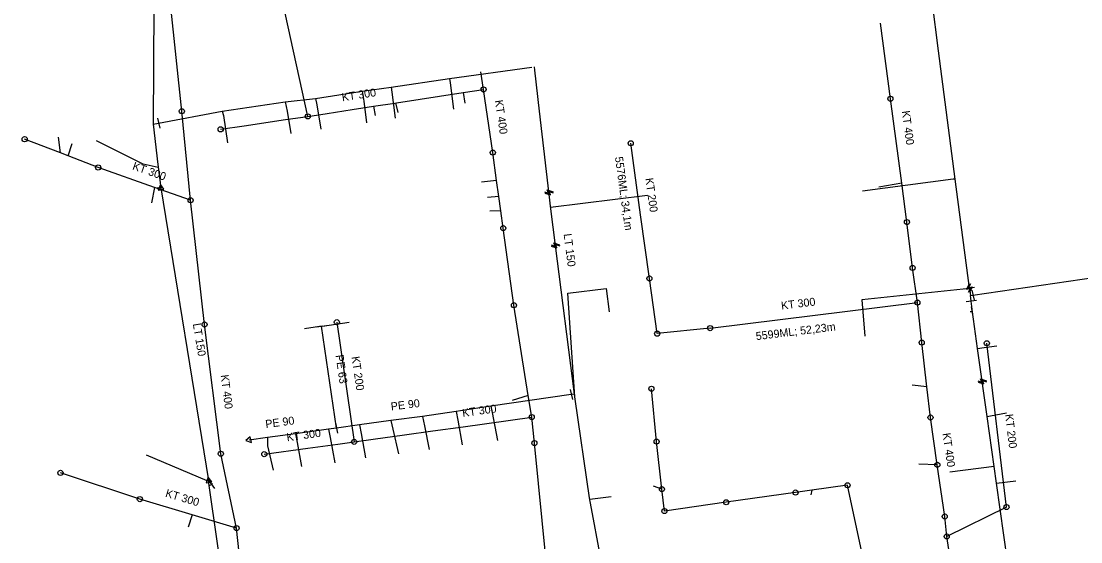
# Model space of a CAD drawing. Extents: x -867696 to -865033, y -1042522 to -1039817.
# Drawn here: x -866602 to -866337.2, y -1040090 to -1039959.9 of the extents above; entities that cross this region are included whole.
import ezdxf

# ---------------------------------------------------------------- set-up
doc = ezdxf.new("R2010")
doc.units = 0
for name, color, linetype in [('KN - jednotna', 7, 'Continuous'), ('KN - popis material', 7, 'Continuous'), ('KN - popis usek delka', 7, 'Continuous'), ('KN - pripojka', 7, 'Continuous'), ('KN - sachta komora', 7, 'Continuous'), ('Level 1', 7, 'Continuous'), ('V - armatura', 7, 'Continuous'), ('V - hydrant', 7, 'Continuous'), ('V - ostatni', 7, 'Continuous'), ('V - popis material', 7, 'Continuous'), ('V - pripojka', 7, 'Continuous'), ('V - rozvadeci', 7, 'Continuous')]:
    doc.layers.add(name, color=color, linetype=linetype)

# ---------------------------------------------------------------- blocks, each defined once
blk = doc.blocks.new('100.M')
at = {"layer": 'Level 1'}
blk.add_circle((0, 0), 1.27, dxfattribs=at)
blk = doc.blocks.new('111')
at = {"layer": 'Level 1'}
for p, q in [((0.42, 0.72), (-0.83, 0)), ((-0.83, 0), (0.42, -0.72)), ((0.42, -0.72), (0.42, 0.72))]:
    blk.add_line(p, q, dxfattribs=at)
blk = doc.blocks.new('147')
at = {"layer": 'Level 1'}
blk.add_line((0, 1.27), (0, -1.27), dxfattribs=at)
blk = doc.blocks.new('156')
at = {"layer": 'Level 1'}
for p, q in [((-0.07, 1.04), (-0.68, -0.3)), ((0.28, 1.04), (-0.19, 0.08)), ((-0.19, 0.08), (0.7, 0.29)), ((0.7, 0.29), (0.02, -1.08)), ((-0.68, -0.3), (0.21, -0.09)), ((0.21, -0.09), (-0.28, -1.08))]:
    blk.add_line(p, q, dxfattribs=at)
blk = doc.blocks.new('150')
at = {"layer": 'Level 1'}
blk.add_line((0, 1.27), (0, -1.27), dxfattribs=at)

msp = doc.modelspace()

# ---------------------------------------------------------------- linework, layer by layer
at = {"layer": 'KN - jednotna'}
for points in [[(-866530.42, -1039983.698), (-866536.083, -1039957.905), (-866537.085, -1039953.342)], [(-866561.894, -1039982.409), (-866564.686, -1039955.577)], [(-866384.771, -1039979.298), (-866387.278, -1039960.4)], [(-866486.47, -1039976.957), (-866487.152, -1039972.545)], [(-866530.42, -1039983.698), (-866525.527, -1039982.947), (-866519.293, -1039981.991), (-866513.939, -1039981.17), (-866508.681, -1039980.364), (-866508.223, -1039980.293), (-866491.558, -1039977.737), (-866486.47, -1039976.957)], [(-866484.157, -1039992.76), (-866486.47, -1039976.957)], [(-866380.63, -1040010.12), (-866381.931, -1040000.41), (-866384.771, -1039979.298)], [(-866559.707, -1040004.648), (-866561.894, -1039982.409)], [(-866552.186, -1039986.929), (-866546.344, -1039986.061), (-866535.938, -1039984.517), (-866530.42, -1039983.698)], [(-866582.782, -1039996.47), (-866590.301, -1039993.583), (-866592.245, -1039992.837), (-866601.176, -1039989.408)], [(-866445.015, -1040024.206), (-866447.202, -1040008.333), (-866449.67, -1039990.42)], [(-866481.542, -1040011.623), (-866482.142, -1040007.293), (-866482.633, -1040003.747), (-866483.194, -1039999.701), (-866484.157, -1039992.76)], [(-866559.707, -1040004.648), (-866568.727, -1040001.452), (-866582.782, -1039996.47)], [(-866556.19, -1040035.705), (-866559.707, -1040004.648)], [(-866478.869, -1040030.903), (-866481.542, -1040011.623)], [(-866379.227, -1040021.559), (-866380.63, -1040010.12)], [(-866378.02, -1040030.23), (-866379.227, -1040021.559)], [(-866443.083, -1040037.995), (-866445.015, -1040024.206)], [(-866474.415, -1040058.848), (-866475.283, -1040053.406), (-866478.869, -1040030.903)], [(-866429.855, -1040036.614), (-866378.02, -1040030.23)], [(-866376.958, -1040040.23), (-866378.02, -1040030.23)], [(-866552.13, -1040067.99), (-866556.19, -1040035.705)], [(-866523.135, -1040035.115), (-866518.82, -1040065.024)], [(-866429.855, -1040036.614), (-866443.083, -1040037.995)], [(-866374.748, -1040058.939), (-866375.653, -1040051.274), (-866376.958, -1040040.23)], [(-866355.75, -1040081.321), (-866360.665, -1040040.386)], [(-866443.21, -1040064.976), (-866444.505, -1040051.755)], [(-866518.82, -1040065.024), (-866514.099, -1040064.368), (-866506.221, -1040063.272), (-866499.129, -1040062.286), (-866491.592, -1040061.237), (-866474.415, -1040058.848)], [(-866473.763, -1040065.329), (-866474.415, -1040058.848)], [(-866373.047, -1040070.778), (-866374.748, -1040058.939)], [(-866541.268, -1040068.103), (-866530.362, -1040066.608), (-866522.911, -1040065.586), (-866518.82, -1040065.024)], [(-866470.797, -1040094.799), (-866473.763, -1040065.329)], [(-866441.88, -1040076.855), (-866443.21, -1040064.976)], [(-866548.186, -1040086.588), (-866552.13, -1040067.99)], [(-866572.376, -1040079.342), (-866592.223, -1040072.779)], [(-866371.193, -1040083.679), (-866373.047, -1040070.778)], [(-866395.498, -1040075.88), (-866404.39, -1040077.124), (-866408.487, -1040077.697)], [(-866385.436, -1040122.877), (-866395.498, -1040075.88)], [(-866441.266, -1040082.335), (-866441.88, -1040076.855)], [(-866408.487, -1040077.697), (-866425.794, -1040080.136)], [(-866548.186, -1040086.588), (-866559.323, -1040083.252), (-866572.376, -1040079.342)], [(-866425.794, -1040080.136), (-866441.266, -1040082.335)], [(-866355.75, -1040081.321), (-866370.701, -1040088.68)], [(-866370.701, -1040088.68), (-866371.193, -1040083.679)], [(-866546.222, -1040105.131), (-866548.186, -1040086.588)], [(-866368.855, -1040100.601), (-866370.701, -1040088.68)]]:
    msp.add_lwpolyline(points, dxfattribs=at)
at = {"layer": 'KN - pripojka'}
for points in [[(-866491.558, -1039977.737), (-866491.116, -1039980.382)], [(-866508.452, -1039980.329), (-866507.928, -1039982.75)], [(-866513.939, -1039981.17), (-866513.589, -1039983.444)], [(-866592.245, -1039992.837), (-866592.738, -1039988.874)], [(-866590.301, -1039993.583), (-866589.272, -1039990.492)], [(-866568.727, -1040001.452), (-866569.441, -1040005.325)], [(-866483.194, -1039999.701), (-866486.956, -1040000.14)], [(-866381.931, -1040000.41), (-866387.692, -1040001.413)], [(-866482.633, -1040003.747), (-866485.454, -1040003.953)], [(-866482.142, -1040007.293), (-866484.876, -1040007.419)], [(-866375.653, -1040051.274), (-866379.33, -1040050.89)], [(-866475.283, -1040053.406), (-866479.33, -1040054.678)], [(-866373.047, -1040070.778), (-866377.705, -1040070.577)], [(-866441.88, -1040076.855), (-866444.018, -1040076.109)], [(-866404.39, -1040077.124), (-866404.643, -1040078.234)], [(-866559.323, -1040083.252), (-866560.313, -1040086.323)]]:
    msp.add_lwpolyline(points, dxfattribs=at)
at = {"layer": 'V - pripojka'}
for points in [[(-866494.976, -1039974.256), (-866494.836, -1039975.325), (-866493.985, -1039981.894)], [(-866516.798, -1039977.428), (-866516.391, -1039979.881), (-866515.708, -1039985.317)], [(-866509.548, -1039976.367), (-866509.409, -1039977.669), (-866508.598, -1039984.132)], [(-866536.072, -1039980.08), (-866535.557, -1039982.433), (-866534.666, -1039987.95)], [(-866528.469, -1039979.196), (-866528.151, -1039980.815), (-866527.162, -1039986.897)], [(-866551.81, -1039982.379), (-866551.488, -1039983.443), (-866550.465, -1039990.32)], [(-866567.77, -1039996.511), (-866571.563, -1039995.635), (-866583.253, -1039989.775)], [(-866567.122, -1040001.576), (-866568.058, -1040001.643)], [(-866368.563, -1039999.396), (-866369.122, -1039999.419), (-866391.757, -1040002.383)], [(-866469.741, -1040006.348), (-866445.511, -1040003.378)], [(-866463.675, -1040053.739), (-866465.399, -1040027.855), (-866455.797, -1040026.733), (-866455.092, -1040032.551)], [(-866365.026, -1040026.719), (-866391.894, -1040029.581), (-866391.199, -1040038.605)], [(-866364.257, -1040032.508), (-866364.38, -1040032.53), (-866364.84, -1040032.55)], [(-866526.74, -1040036.081), (-866527.482, -1040036.182), (-866531.212, -1040036.797)], [(-866526.74, -1040036.081), (-866520.097, -1040035.163)], [(-866362.982, -1040041.678), (-866361.3, -1040041.46), (-866358.144, -1040041.023)], [(-866493.32, -1040057.406), (-866492.902, -1040059.591), (-866491.779, -1040065.758)], [(-866484.69, -1040056.125), (-866484.352, -1040057.682), (-866482.959, -1040064.705)], [(-866509.679, -1040059.682), (-866509.129, -1040061.889), (-866507.71, -1040067.996)], [(-866501.699, -1040058.674), (-866501.253, -1040061.036), (-866500.074, -1040066.943)], [(-866360.61, -1040058.726), (-866359.736, -1040058.5), (-866355.745, -1040057.747)], [(-866525.194, -1040061.835), (-866524.818, -1040063.962), (-866523.64, -1040070.234)], [(-866517.478, -1040060.787), (-866517.046, -1040062.968), (-866516.004, -1040069.049)], [(-866540.465, -1040063.953), (-866540.437, -1040066.061), (-866539.044, -1040072.078)], [(-866533.499, -1040063.037), (-866533.073, -1040065.152), (-866531.934, -1040071.156)], [(-866555.186, -1040074.717), (-866555.581, -1040074.774), (-866570.72, -1040068.376)], [(-866358.843, -1040071.216), (-866369.946, -1040072.575)], [(-866555.05, -1040075.918), (-866554.474, -1040075.661), (-866554.263, -1040075.441)], [(-866358.251, -1040075.396), (-866353.446, -1040074.767)], [(-866459.92, -1040079.312), (-866454.563, -1040078.654)]]:
    msp.add_lwpolyline(points, dxfattribs=at)
at = {"layer": 'V - rozvadeci'}
for points in [[(-866365.046, -1040026.608), (-866368.563, -1039999.396), (-866372.715, -1039967.277), (-866374.319, -1039954.861), (-866375.084, -1039948.941), (-866379.24, -1039916.789), (-866379.95, -1039911.3), (-866380.406, -1039907.768), (-866380.863, -1039904.235), (-866386.772, -1039858.514), (-866389.1, -1039840.505)], [(-866581.76, -1039885.37), (-866577.81, -1039911.421), (-866577.678, -1039912.286), (-866575.523, -1039926.5), (-866570.436, -1039929.029), (-866568.784, -1039941.173), (-866569.051, -1039985.606)], [(-866567.695, -1039985.362), (-866551.81, -1039982.379), (-866536.072, -1039980.08), (-866528.469, -1039979.196), (-866516.798, -1039977.428), (-866509.548, -1039976.367), (-866494.976, -1039974.256), (-866474.393, -1039971.416)], [(-866468.52, -1040015.935), (-866469.689, -1040006.793), (-866472.497, -1039982.406), (-866473.676, -1039972.163), (-866473.774, -1039971.33)], [(-866569.051, -1039985.606), (-866567.695, -1039985.362)], [(-866569.051, -1039985.606), (-866567.874, -1039995.697), (-866567.122, -1040001.576)], [(-866567.122, -1040001.576), (-866555.186, -1040074.717)], [(-866463.766, -1040053.122), (-866468.52, -1040015.935)], [(-866364.138, -1040028.354), (-866285.566, -1040016.9)], [(-866365.046, -1040026.608), (-866365.026, -1040026.719), (-866364.716, -1040028.45)], [(-866364.716, -1040028.45), (-866364.138, -1040028.354)], [(-866364.55, -1040029.89), (-866364.655, -1040029.147), (-866364.716, -1040028.45)], [(-866354.578, -1040101.362), (-866358.251, -1040075.396), (-866358.843, -1040071.216), (-866360.61, -1040058.726), (-866362.982, -1040041.678), (-866364.257, -1040032.508), (-866364.55, -1040029.89)], [(-866523.252, -1040061.571), (-866526.968, -1040036.112)], [(-866464.535, -1040053.232), (-866484.69, -1040056.125), (-866493.32, -1040057.406), (-866501.699, -1040058.674), (-866509.679, -1040059.682), (-866517.478, -1040060.787), (-866523.252, -1040061.571)], [(-866463.766, -1040053.122), (-866464.535, -1040053.232)], [(-866456.9, -1040095.51), (-866459.976, -1040079.013), (-866463.58, -1040054.387), (-866463.766, -1040053.122)], [(-866523.252, -1040061.571), (-866525.194, -1040061.835), (-866533.499, -1040063.037), (-866540.465, -1040063.953), (-866545.063, -1040064.572)], [(-866550.505, -1040107.052), (-866550.962, -1040104.31), (-866555.05, -1040075.918), (-866555.186, -1040074.717)]]:
    msp.add_lwpolyline(points, dxfattribs=at)

# ---------------------------------------------------------------- block references
at = {"layer": 'KN - sachta komora'}
for p, xscale, yscale, rotation in [((-866486.47, -1039976.957), 0.5000000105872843, 0.5000000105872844, -81.00000039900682), ((-866384.771, -1039979.298), 0.49999999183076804, 0.49999999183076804, 98.00000038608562), ((-866561.894, -1039982.409), 0.5005608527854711, 0.5005608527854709, 96.5826098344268), ((-866530.42, -1039983.698), 0.5041888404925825, 0.5041888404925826, -168.37362119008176), ((-866601.176, -1039989.408), 0.5148474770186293, 0.5148474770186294, 155.86620948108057), ((-866552.186, -1039986.929), 0.5041888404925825, 0.5041888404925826, 11.626378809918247), ((-866449.67, -1039990.42), 0.49999999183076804, 0.49999999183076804, 98.00000038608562), ((-866484.157, -1039992.76), 0.5000000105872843, 0.5000000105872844, -81.00000039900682), ((-866582.782, -1039996.47), 0.5148474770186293, 0.5148474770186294, 155.86620948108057), ((-866559.707, -1040004.648), 0.500095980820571, 0.500095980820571, 97.08900113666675), ((-866380.63, -1040010.12), 0.49999999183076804, 0.49999999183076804, 98.00000038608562), ((-866481.542, -1040011.623), 0.49999999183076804, 0.49999999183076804, -81.99999961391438), ((-866379.227, -1040021.559), 0.49999999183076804, 0.49999999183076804, -81.99999961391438), ((-866445.015, -1040024.206), 0.49999999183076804, 0.49999999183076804, -81.99999961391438), ((-866478.869, -1040030.903), 0.5000000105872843, 0.5000000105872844, -81.00000039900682), ((-866378.02, -1040030.23), 0.5000000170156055, 0.5000000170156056, -38.000000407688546), ((-866556.19, -1040035.705), 0.500095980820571, 0.500095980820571, -82.91099886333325), ((-866523.135, -1040035.115), 0.5000000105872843, 0.5000000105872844, -81.00000039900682), ((-866429.855, -1040036.614), 0.5049058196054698, 0.5049058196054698, 10.610301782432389), ((-866443.083, -1040037.995), 0.5000000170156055, 0.5000000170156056, 141.99999959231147), ((-866376.958, -1040040.23), 0.500095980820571, 0.500095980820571, -82.91099886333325), ((-866360.665, -1040040.386), 0.500095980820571, 0.500095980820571, 97.08900113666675), ((-866444.505, -1040051.755), 0.5005608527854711, 0.5005608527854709, 96.5826098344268), ((-866474.415, -1040058.848), 0.49999999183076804, 0.49999999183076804, -81.99999961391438), ((-866374.748, -1040058.939), 0.49999999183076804, 0.49999999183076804, -81.99999961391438), ((-866518.82, -1040065.024), 0.5046025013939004, 0.5046025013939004, -168.88308178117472), ((-866473.763, -1040065.329), 0.5005608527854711, 0.5005608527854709, -83.41739016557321), ((-866443.21, -1040064.976), 0.5005608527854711, 0.5005608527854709, 96.5826098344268), ((-866552.13, -1040067.99), 0.49999998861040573, 0.4999999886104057, -79.99999971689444), ((-866541.268, -1040068.103), 0.5046025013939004, 0.5046025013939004, 11.116918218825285), ((-866373.047, -1040070.778), 0.5000000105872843, 0.5000000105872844, -81.00000039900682), ((-866592.223, -1040072.779), 0.516753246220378, 0.516753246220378, 156.95871826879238), ((-866395.498, -1040075.88), 0.4999999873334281, 0.499999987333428, 145.99999954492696), ((-866572.376, -1040079.342), 0.517562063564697, 0.5175620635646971, 157.49634583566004), ((-866441.88, -1040076.855), 0.500095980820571, 0.500095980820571, -82.91099886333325), ((-866408.487, -1040077.697), 0.5046025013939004, 0.5046025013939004, -168.88308178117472), ((-866425.794, -1040080.136), 0.5041888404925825, 0.5041888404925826, -168.37362119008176), ((-866355.75, -1040081.321), 0.49999998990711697, 0.49999998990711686, 61.99999866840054), ((-866441.266, -1040082.335), 0.49999999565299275, 0.4999999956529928, 142.99999806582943), ((-866371.193, -1040083.679), 0.500095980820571, 0.500095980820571, -82.91099886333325), ((-866548.186, -1040086.588), 0.49999998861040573, 0.4999999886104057, -79.99999971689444), ((-866370.701, -1040088.68), 0.49999999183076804, 0.49999999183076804, -81.99999961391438)]:
    msp.add_blockref('100.M', p, dxfattribs=dict(at, xscale=xscale, yscale=yscale, rotation=rotation))
at = {"layer": 'V - armatura'}
for p, xscale, yscale, rotation in [((-866567.695, -1039985.362), 1.0060666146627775, 1.0060666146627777, 12.654735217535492), ((-866365.046, -1040026.608), 1.0000000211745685, 1.0000000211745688, 98.99999960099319), ((-866364.138, -1040028.354), 1.008377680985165, 1.0083776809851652, 11.626378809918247), ((-866364.55, -1040029.89), 0.9999999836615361, 0.9999999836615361, -81.99999961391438), ((-866526.968, -1040036.112), 1.0000000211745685, 1.0000000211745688, 98.99999960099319), ((-866464.535, -1040053.232), 1.008377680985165, 1.0083776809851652, 11.626378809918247), ((-866523.252, -1040061.571), 1.0092050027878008, 1.0092050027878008, 11.116918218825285)]:
    msp.add_blockref('147', p, dxfattribs=dict(at, xscale=xscale, yscale=yscale, rotation=rotation))
at = {"layer": 'V - hydrant'}
for p, xscale, yscale, rotation in [((-866364.38, -1040032.53), 1.0098116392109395, 1.0098116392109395, 10.610301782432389), ((-866554.474, -1040075.661), 1.000000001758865, 1.000000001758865, 35.99999933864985)]:
    msp.add_blockref('150', p, dxfattribs=dict(at, xscale=xscale, yscale=yscale, rotation=rotation))
at = {"layer": 'V - ostatni'}
for name, p, xscale, yscale, rotation in [('111', (-866567.122, -1040001.576), 1.0000000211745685, 1.0000000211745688, -81.00000039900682), ('156', (-866470.161, -1040002.692), 0.9999999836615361, 0.9999999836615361, 98.00000038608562), ('156', (-866468.52, -1040015.94), 0.9999999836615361, 0.9999999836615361, 98.00000038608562), ('156', (-866361.834, -1040049.929), 0.9999999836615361, 0.9999999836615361, 98.00000038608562), ('111', (-866545.063, -1040064.572), 1.0092050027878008, 1.0092050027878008, 11.116918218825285), ('111', (-866555.186, -1040074.717), 0.9999999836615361, 0.9999999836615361, -81.99999961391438)]:
    msp.add_blockref(name, p, dxfattribs=dict(at, xscale=xscale, yscale=yscale, rotation=rotation))
msp.add_blockref('156', (-866365.046, -1040026.608), dxfattribs=at)

# ---------------------------------------------------------------- texts
at = {"layer": 'KN - popis material'}
for s, rotation, p in [('KT 300', 8.72, (-866521.756, -1039979.941)), ('KT 400', 278.33, (-866483.639, -1039979.731)), ('KT 400', 277.66, (-866381.932, -1039982.397)), ('KT 300', 340.49, (-866574.385, -1039996.901)), ('KT 200', 277.84, (-866446.036, -1039999.205)), ('KT 300', 7.02, (-866411.983, -1040031.995)), ('KT 200', 278.21, (-866519.458, -1040043.792)), ('KT 400', 277.17, (-866552.179, -1040048.361)), ('KT 300', 7.92, (-866491.662, -1040058.824)), ('KT 200', 276.85, (-866356.111, -1040058.189)), ('KT 300', 7.81, (-866535.568, -1040064.9)), ('KT 400', 278.18, (-866371.75, -1040062.928)), ('KT 300', 343.32, (-866566.15, -1040078.701))]:
    msp.add_text(s, height=2, rotation=rotation, dxfattribs=at).set_placement(p)
at = {"layer": 'KN - popis usek delka'}
for s, rotation, p in [('5576ML; 34,1m', 277.84, (-866453.633, -1039993.892)), ('5599ML; 52,23m', 7.02, (-866418.298, -1040039.624))]:
    msp.add_text(s, height=1.99999, rotation=rotation, dxfattribs=at).set_placement(p)
at = {"layer": 'V - popis material'}
for s, rotation, p in [('LT 150', 277.29, (-866466.457, -1040013.099)), ('LT 150', 279.27, (-866559.147, -1040035.545)), ('PE 63', 278.3, (-866523.478, -1040043.401)), ('PE 90', 7.2, (-866509.53, -1040057.209)), ('PE 90', 7.49, (-866540.873, -1040061.586))]:
    msp.add_text(s, height=2, rotation=rotation, dxfattribs=at).set_placement(p)

doc.saveas('drawing.dxf')
